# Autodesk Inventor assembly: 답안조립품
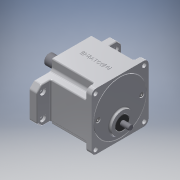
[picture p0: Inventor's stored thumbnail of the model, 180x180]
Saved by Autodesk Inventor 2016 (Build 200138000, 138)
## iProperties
Created: 2017-01
Part Number: 답안조립품
Material: 일반
Document SubType Name: Assembly
Designer: Owner
Author: Owner
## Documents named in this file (10)
- C:\Users\Owner\Desktop\470111V1008\답안조립품.iam
- C:\Users\Owner\Desktop\470111V1008\본체.ipt
- C:\Users\Owner\Desktop\470111V1008\메인축.ipt
- C:\Users\Owner\Desktop\470111V1008\베어링 608.ipt
- C:\Users\Owner\Desktop\470111V1008\베어링 6003.ipt
- C:\Users\Owner\Desktop\470111V1008\볼트 M4 x 10.ipt
- C:\Users\Owner\Desktop\470111V1008\서브축.ipt
- C:\Users\Owner\Desktop\470111V1008\오일실 8 22 7.ipt
- C:\Users\Owner\Desktop\470111V1008\오일실 17 32 8.ipt
- C:\Users\Owner\Desktop\470111V1008\커버.ipt
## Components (4 placed, 1 different names)
1. ISO 4762 M4 x 10:1
2. ISO 4762 M4 x 10:2
3. ISO 4762 M4 x 10:3
4. ISO 4762 M4 x 10:4
